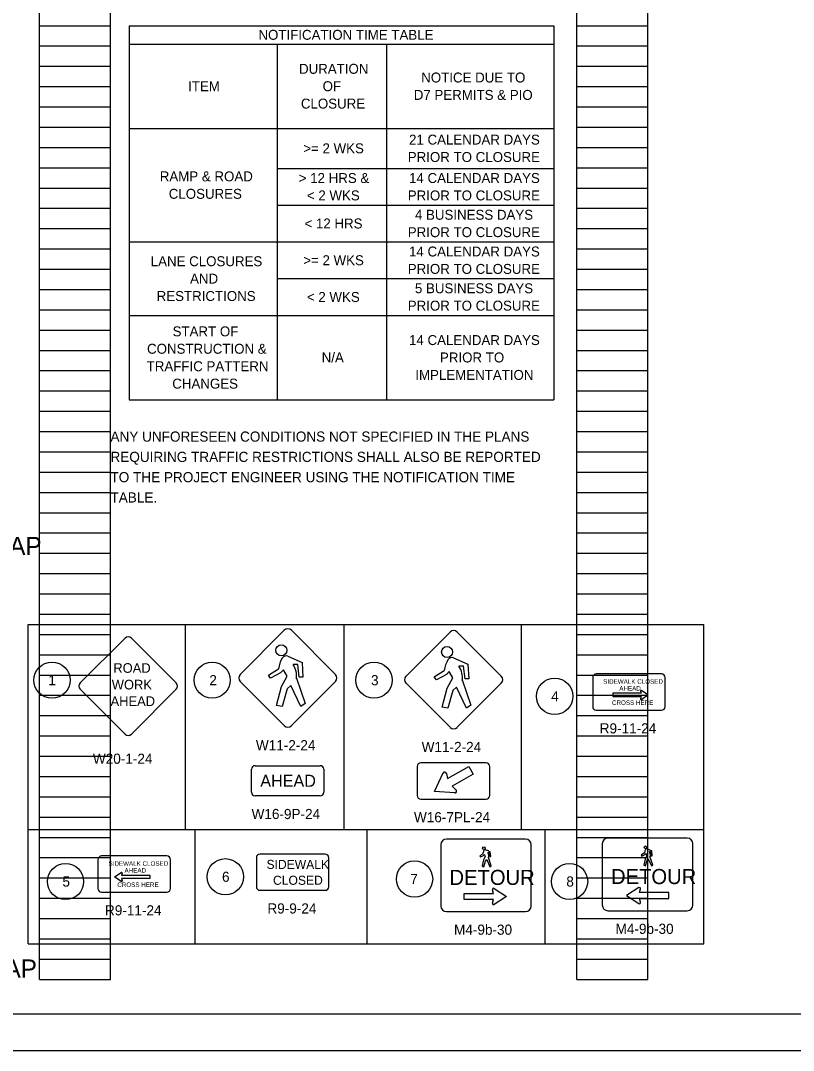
# Model space of a CAD drawing. Extents: x 0 to 34, y 0 to 22.
# Drawn here: x 8.58 to 19.25, y 0 to 14.21 of the extents above; entities that cross this region are included whole.
import ezdxf

# ---------------------------------------------------------------- set-up
doc = ezdxf.new("R2010")
doc.units = 0
for name, color, linetype in [('BR_P_Gen_Text', 7, 'Continuous'), ('Default', 7, 'Continuous'), ('SC_Scratch1', 7, 'Continuous'), ('SH_Border', 7, 'Continuous'), ('SH_Cut_Line', 7, 'Continuous'), ('SH_Text', 7, 'Continuous'), ('SN_P_Signs', 7, 'Continuous'), ('SN_P_Text', 7, 'Continuous')]:
    doc.layers.add(name, color=color, linetype=linetype)

msp = doc.modelspace()

# ---------------------------------------------------------------- linework, layer by layer
at = {"layer": 'SC_Scratch1'}
for p, q in [((8.84, 0.98), (8.84, 21.14)), ((9.82, 0.98), (9.82, 21.14)), ((16.26, 0.98), (16.26, 21.14)), ((17.24, 0.98), (17.24, 21.14)), ((8.84, 14.14), (9.82, 14.14)), ((16.26, 14.14), (17.24, 14.14)), ((8.84, 13.86), (9.82, 13.86)), ((16.26, 13.86), (17.24, 13.86)), ((8.84, 13.58), (9.82, 13.58)), ((16.26, 13.58), (17.24, 13.58)), ((8.84, 13.3), (9.82, 13.3)), ((16.26, 13.3), (17.24, 13.3)), ((8.84, 13.02), (9.82, 13.02)), ((16.26, 13.02), (17.24, 13.02)), ((8.84, 12.74), (9.82, 12.74)), ((16.26, 12.74), (17.24, 12.74)), ((8.84, 12.46), (9.82, 12.46)), ((16.26, 12.46), (17.24, 12.46)), ((8.84, 12.18), (9.82, 12.18)), ((16.26, 12.18), (17.24, 12.18)), ((8.84, 11.9), (9.82, 11.9)), ((16.26, 11.9), (17.24, 11.9)), ((8.84, 11.62), (9.82, 11.62)), ((16.26, 11.62), (17.24, 11.62)), ((8.84, 11.34), (9.82, 11.34)), ((16.26, 11.34), (17.24, 11.34)), ((8.84, 11.06), (9.82, 11.06)), ((16.26, 11.06), (17.24, 11.06)), ((8.84, 10.78), (9.82, 10.78)), ((16.26, 10.78), (17.24, 10.78)), ((8.84, 10.5), (9.82, 10.5)), ((16.26, 10.5), (17.24, 10.5)), ((8.84, 10.22), (9.82, 10.22)), ((16.26, 10.22), (17.24, 10.22)), ((8.84, 9.94), (9.82, 9.94)), ((16.26, 9.94), (17.24, 9.94)), ((8.84, 9.66), (9.82, 9.66)), ((16.26, 9.66), (17.24, 9.66)), ((8.84, 9.38), (9.82, 9.38)), ((16.26, 9.38), (17.24, 9.38)), ((8.84, 9.1), (9.82, 9.1)), ((16.26, 9.1), (17.24, 9.1)), ((8.84, 8.82), (9.82, 8.82)), ((16.26, 8.82), (17.24, 8.82)), ((8.84, 8.54), (9.82, 8.54)), ((16.26, 8.54), (17.24, 8.54)), ((8.84, 8.26), (9.82, 8.26)), ((16.26, 8.26), (17.24, 8.26)), ((8.84, 7.98), (9.82, 7.98)), ((16.26, 7.98), (17.24, 7.98)), ((8.84, 7.7), (9.82, 7.7)), ((16.26, 7.7), (17.24, 7.7)), ((8.84, 7.42), (9.82, 7.42)), ((16.26, 7.42), (17.24, 7.42)), ((8.84, 7.14), (9.82, 7.14)), ((16.26, 7.14), (17.24, 7.14)), ((8.84, 6.86), (9.82, 6.86)), ((16.26, 6.86), (17.24, 6.86)), ((8.84, 6.58), (9.82, 6.58)), ((16.26, 6.58), (17.24, 6.58)), ((8.84, 6.3), (9.82, 6.3)), ((16.26, 6.3), (17.24, 6.3)), ((8.84, 6.02), (9.82, 6.02)), ((16.26, 6.02), (17.24, 6.02)), ((8.84, 5.74), (9.82, 5.74)), ((16.26, 5.74), (17.24, 5.74)), ((8.84, 5.46), (9.82, 5.46)), ((16.26, 5.46), (17.24, 5.46)), ((8.84, 5.18), (9.82, 5.18)), ((16.26, 5.18), (17.24, 5.18)), ((8.84, 4.9), (9.82, 4.9)), ((16.26, 4.9), (17.24, 4.9)), ((8.84, 4.62), (9.82, 4.62)), ((16.26, 4.62), (17.24, 4.62)), ((8.84, 4.34), (9.82, 4.34)), ((16.26, 4.34), (17.24, 4.34)), ((8.84, 4.06), (9.82, 4.06)), ((16.26, 4.06), (17.24, 4.06)), ((8.84, 3.78), (9.82, 3.78)), ((16.26, 3.78), (17.24, 3.78)), ((8.84, 3.5), (9.82, 3.5)), ((16.26, 3.5), (17.24, 3.5)), ((8.84, 3.22), (9.82, 3.22)), ((16.26, 3.22), (17.24, 3.22)), ((8.84, 2.94), (9.82, 2.94)), ((16.26, 2.94), (17.24, 2.94)), ((8.84, 2.66), (9.82, 2.66)), ((16.26, 2.66), (17.24, 2.66)), ((8.84, 2.38), (9.82, 2.38)), ((16.26, 2.38), (17.24, 2.38)), ((8.84, 2.1), (9.82, 2.1)), ((16.26, 2.1), (17.24, 2.1)), ((8.84, 1.82), (9.82, 1.82)), ((16.26, 1.82), (17.24, 1.82)), ((8.84, 1.54), (9.82, 1.54)), ((16.26, 1.54), (17.24, 1.54)), ((8.84, 1.26), (9.82, 1.26)), ((16.26, 1.26), (17.24, 1.26)), ((8.84, 0.98), (9.82, 0.98)), ((16.26, 0.98), (17.24, 0.98))]:
    msp.add_line(p, q, dxfattribs=at)
at = {"layer": 'SH_Border'}
msp.add_lwpolyline([(1.5, 21.5), (33.5, 21.5), (33.5, 0.5), (1.5, 0.5)], close=True, dxfattribs=at)
at = {"layer": 'SH_Cut_Line'}
msp.add_lwpolyline([(0, 0), (34, 0), (34, 22), (0, 22)], close=True, dxfattribs=at)
at = {"layer": 'SH_Text'}
for p, q in [((10.079, 14.14), (15.94, 14.14)), ((10.079, 14.14), (10.079, 8.979)), ((15.94, 14.14), (15.94, 8.979)), ((10.079, 13.886), (15.94, 13.886)), ((12.122, 13.886), (12.122, 8.979)), ((13.629, 13.886), (13.629, 8.979)), ((10.079, 12.723), (15.94, 12.723)), ((12.122, 12.171), (15.94, 12.171)), ((12.122, 11.664), (15.94, 11.664)), ((10.079, 11.157), (15.94, 11.157)), ((12.122, 10.65), (15.94, 10.65)), ((10.079, 10.143), (15.94, 10.143)), ((10.079, 8.979), (15.94, 8.979)), ((8.684, 1.469), (8.684, 5.876)), ((8.684, 5.876), (18.009, 5.876)), ((10.857, 3.047), (10.857, 5.876)), ((13.045, 3.047), (13.045, 5.876)), ((15.496, 3.047), (15.496, 5.876)), ((18.009, 1.469), (18.009, 5.876)), ((8.684, 3.047), (18.009, 3.047)), ((10.991, 1.469), (10.991, 3.047)), ((13.366, 1.469), (13.366, 3.047)), ((15.819, 1.469), (15.819, 3.047)), ((8.684, 1.469), (18.009, 1.469))]:
    msp.add_line(p, q, dxfattribs=at)
for centre in [(9.013, 5.109), (11.224, 5.109), (13.458, 5.109), (15.952, 4.886), (9.2, 2.33), (11.406, 2.396), (14.018, 2.365), (16.158, 2.331)]:
    msp.add_circle(centre, 0.25, dxfattribs=at)
at = {"layer": 'SN_P_Signs'}
for p, q in [((12.268, 5.441), (12.466, 5.354)), ((14.557, 5.418), (14.755, 5.331)), ((12.001, 5.18), (12.14, 5.267)), ((12.407, 5.325), (12.342, 5.325)), ((12.427, 5.151), (12.407, 5.325)), ((12.466, 5.354), (12.476, 5.151)), ((14.695, 5.302), (14.63, 5.302)), ((14.715, 5.127), (14.695, 5.302)), ((14.755, 5.331), (14.765, 5.127)), ((12.031, 5.136), (12.001, 5.18)), ((12.169, 5.209), (12.031, 5.136)), ((12.209, 5.253), (12.169, 5.209)), ((12.179, 5.02), (12.259, 5.165)), ((12.259, 5.165), (12.209, 5.253)), ((12.387, 5.136), (12.506, 4.788)), ((12.476, 5.151), (12.427, 5.151)), ((14.289, 5.156), (14.428, 5.244)), ((14.319, 5.113), (14.289, 5.156)), ((14.458, 5.185), (14.319, 5.113)), ((14.497, 5.229), (14.458, 5.185)), ((14.468, 4.997), (14.547, 5.142)), ((14.547, 5.142), (14.497, 5.229)), ((14.765, 5.127), (14.715, 5.127)), ((12.11, 4.759), (12.179, 5.02)), ((12.259, 4.991), (12.189, 4.745)), ((12.308, 5.035), (12.259, 4.991)), ((12.447, 4.745), (12.308, 5.035)), ((14.398, 4.735), (14.468, 4.997)), ((14.596, 5.011), (14.547, 4.968)), ((14.735, 4.721), (14.596, 5.011)), ((14.676, 5.113), (14.794, 4.764)), ((14.547, 4.968), (14.478, 4.721)), ((17.145, 4.928), (16.755, 4.928)), ((16.755, 4.928), (16.755, 4.882)), ((17.137, 4.957), (17.146, 4.928)), ((17.146, 4.882), (17.137, 4.853)), ((17.146, 4.928), (17.145, 4.928)), ((17.239, 4.905), (17.151, 4.967)), ((17.151, 4.843), (17.239, 4.905)), ((12.189, 4.745), (12.11, 4.759)), ((12.506, 4.788), (12.447, 4.745)), ((14.478, 4.721), (14.398, 4.735)), ((14.794, 4.764), (14.735, 4.721)), ((14.475, 3.75), (14.766, 3.918)), ((14.766, 3.918), (14.827, 3.813)), ((14.459, 3.822), (14.475, 3.75)), ((14.827, 3.813), (14.535, 3.645)), ((14.535, 3.645), (14.59, 3.595)), ((14.572, 3.553), (14.572, 3.553)), ((14.961, 2.716), (14.917, 2.682)), ((14.97, 2.69), (14.98, 2.708)), ((14.98, 2.708), (14.994, 2.678)), ((15.031, 2.732), (15.047, 2.732)), ((15.047, 2.732), (15.055, 2.675)), ((15.069, 2.674), (15.064, 2.74)), ((15.064, 2.74), (15.064, 2.74)), ((17.192, 2.727), (17.147, 2.694)), ((17.156, 2.681), (17.2, 2.701)), ((17.2, 2.701), (17.21, 2.72)), ((17.21, 2.72), (17.225, 2.69)), ((17.261, 2.744), (17.277, 2.743)), ((17.277, 2.743), (17.285, 2.687)), ((17.299, 2.686), (17.294, 2.752)), ((17.294, 2.752), (17.294, 2.752)), ((14.917, 2.682), (14.926, 2.669)), ((14.926, 2.669), (14.97, 2.69)), ((14.97, 2.629), (14.952, 2.546)), ((14.984, 2.658), (14.97, 2.629)), ((14.975, 2.534), (14.998, 2.613)), ((14.994, 2.678), (14.984, 2.658)), ((14.998, 2.613), (15.014, 2.633)), ((15.014, 2.633), (15.057, 2.533)), ((15.038, 2.663), (15.04, 2.665)), ((15.077, 2.547), (15.038, 2.663)), ((15.055, 2.675), (15.069, 2.674)), ((17.147, 2.694), (17.156, 2.681)), ((17.201, 2.641), (17.182, 2.558)), ((17.214, 2.67), (17.201, 2.641)), ((17.205, 2.546), (17.228, 2.624)), ((17.225, 2.69), (17.214, 2.67)), ((17.228, 2.624), (17.244, 2.644)), ((17.244, 2.644), (17.288, 2.545)), ((17.268, 2.675), (17.27, 2.677)), ((17.307, 2.559), (17.268, 2.675)), ((17.285, 2.687), (17.299, 2.686)), ((17.288, 2.545), (17.307, 2.559)), ((9.878, 2.394), (9.966, 2.456)), ((9.98, 2.445), (9.971, 2.417)), ((9.971, 2.417), (9.972, 2.417)), ((9.972, 2.417), (10.362, 2.417)), ((10.362, 2.417), (10.362, 2.37)), ((14.952, 2.546), (14.975, 2.534)), ((15.057, 2.533), (15.077, 2.547)), ((17.182, 2.558), (17.205, 2.546)), ((9.966, 2.331), (9.878, 2.394)), ((9.971, 2.37), (9.98, 2.342)), ((14.705, 2.083), (14.705, 2.166)), ((14.705, 2.166), (15.109, 2.166)), ((15.109, 2.166), (15.093, 2.216)), ((15.117, 2.234), (15.288, 2.124)), ((17.114, 2.246), (16.943, 2.136)), ((16.943, 2.136), (17.114, 2.027)), ((17.122, 2.178), (17.138, 2.228)), ((17.526, 2.178), (17.122, 2.178)), ((17.526, 2.094), (17.526, 2.178)), ((15.109, 2.083), (14.705, 2.083)), ((15.093, 2.032), (15.109, 2.083)), ((15.288, 2.124), (15.117, 2.015)), ((17.138, 2.044), (17.122, 2.094)), ((17.122, 2.094), (17.526, 2.094))]:
    msp.add_line(p, q, dxfattribs=at)
for points in [[(9.403, 5.071), (10.021, 5.69)], [(10.11, 5.69), (10.729, 5.071)], [(11.611, 5.188), (12.219, 5.797)], [(12.318, 5.797), (12.927, 5.188)], [(13.9, 5.165), (14.508, 5.773)], [(14.607, 5.773), (15.215, 5.165)], [(16.477, 5.144), (16.477, 4.744)], [(17.427, 5.194), (16.527, 5.194)], [(17.477, 4.744), (17.477, 5.144)], [(10.021, 4.364), (9.403, 4.983)], [(10.729, 4.983), (10.11, 4.364)], [(12.219, 4.481), (11.611, 5.089)], [(12.927, 5.089), (12.318, 4.481)], [(14.508, 4.458), (13.9, 5.066)], [(15.215, 5.066), (14.607, 4.458)], [(16.755, 4.882), (17.145, 4.882)], [(16.527, 4.694), (17.427, 4.694)], [(11.766, 3.562), (11.766, 3.879)], [(11.816, 3.929), (12.716, 3.929)], [(12.766, 3.879), (12.766, 3.562)], [(14.055, 3.918), (14.055, 3.518)], [(15.005, 3.968), (14.105, 3.968)], [(15.055, 3.518), (15.055, 3.918)], [(14.572, 3.553), (14.291, 3.574), (14.413, 3.828)], [(12.716, 3.512), (11.816, 3.512)], [(14.105, 3.468), (15.005, 3.468)], [(15.551, 2.916), (14.457, 2.916)], [(16.61, 2.85), (16.61, 2.006)], [(17.782, 2.928), (16.688, 2.928)], [(17.86, 2.006), (17.86, 2.85)], [(12.784, 2.709), (11.884, 2.709)], [(14.379, 2.838), (14.379, 1.994)], [(15.629, 1.994), (15.629, 2.838)], [(9.648, 2.633), (9.648, 2.233)], [(10.598, 2.683), (9.698, 2.683)], [(10.648, 2.233), (10.648, 2.633)], [(11.834, 2.659), (11.834, 2.259)], [(12.834, 2.259), (12.834, 2.659)], [(10.362, 2.37), (9.972, 2.37)], [(9.698, 2.183), (10.598, 2.183)], [(11.884, 2.209), (12.784, 2.209)], [(14.457, 1.916), (15.551, 1.916)], [(16.688, 1.928), (17.782, 1.928)]]:
    msp.add_lwpolyline(points, dxfattribs=at)
for centre, radius in [((12.179, 5.521), 0.0758), ((14.467, 5.497), 0.0758), ((14.974, 2.79), 0.0191), ((17.205, 2.802), 0.0191)]:
    msp.add_circle(centre, radius, dxfattribs=at)
for centre, radius, start, end in [((10.066, 5.645), 0.0625, 45, 135), ((12.269, 5.747), 0.07, 45, 135), ((14.557, 5.723), 0.07, 45, 135), ((12.617, 5.183), 0.485, 151.5411, 170.0317), ((12.251, 5.368), 0.0751, 76.2441, 142.495), ((14.539, 5.345), 0.0751, 76.2441, 142.495), ((12.108, 5.167), 0.282, 351.8502, 34.0609), ((14.905, 5.16), 0.485, 151.5411, 170.0317), ((14.396, 5.143), 0.282, 351.8502, 34.0609), ((11.661, 5.139), 0.07, 135, 225), ((12.877, 5.139), 0.07, 315, 45), ((13.949, 5.115), 0.07, 135, 225), ((15.165, 5.115), 0.07, 315, 45), ((16.527, 5.144), 0.05, 90, 180), ((17.427, 5.144), 0.05, 0, 90), ((9.447, 5.027), 0.0625, 135, 225), ((10.684, 5.027), 0.0625, 315, 45), ((17.145, 4.96), 0.00912, 54.9207, 197.6378), ((17.145, 4.85), 0.00912, 162.3622, 305.0792), ((16.527, 4.744), 0.05, 180, 270), ((17.427, 4.744), 0.05, 270, 0), ((12.269, 4.531), 0.07, 225, 315), ((14.557, 4.507), 0.07, 225, 315), ((10.066, 4.408), 0.0625, 225, 315), ((11.816, 3.879), 0.05, 90, 180), ((12.716, 3.879), 0.05, 0, 90), ((14.105, 3.918), 0.05, 90, 180), ((14.435, 3.817), 0.0243, 12.1872, 154.3237), ((15.005, 3.918), 0.05, 0, 90), ((11.816, 3.562), 0.05, 180, 270), ((12.716, 3.562), 0.05, 270, 360), ((14.574, 3.577), 0.0243, 265.6763, 47.8128), ((14.105, 3.518), 0.05, 180, 270), ((15.005, 3.518), 0.05, 270, 360), ((14.457, 2.838), 0.0781, 90, 180), ((15.551, 2.838), 0.0781, 0, 90), ((16.688, 2.85), 0.0781, 90, 180), ((17.782, 2.85), 0.0781, 0, 90), ((11.884, 2.659), 0.05, 90, 180), ((12.784, 2.659), 0.05, 0, 90), ((9.698, 2.633), 0.05, 90, 180), ((10.598, 2.633), 0.05, 0, 90), ((9.972, 2.448), 0.00912, 342.3622, 125.0793), ((9.972, 2.339), 0.00912, 234.9208, 17.6378), ((9.698, 2.233), 0.05, 180, 270), ((10.598, 2.233), 0.05, 270, 0), ((11.884, 2.259), 0.05, 180, 270), ((12.784, 2.259), 0.05, 270, 0), ((15.108, 2.221), 0.0156, 57.4015, 196.9519), ((17.123, 2.232), 0.0156, 343.0481, 122.5985), ((14.457, 1.994), 0.0781, 180, 270), ((15.108, 2.028), 0.0156, 163.0481, 302.5985), ((15.551, 1.994), 0.0781, 270, 0), ((16.688, 2.006), 0.0781, 180, 270), ((17.123, 2.04), 0.0156, 237.4015, 16.9519), ((17.782, 2.006), 0.0781, 270, 0)]:
    msp.add_arc(centre, radius, start, end, dxfattribs=at)
for points in [[(15.064, 2.74), (15.044, 2.749), (15.013, 2.763), (15.002, 2.768), (14.998, 2.769), (14.995, 2.769), (14.986, 2.769), (14.974, 2.758), (14.968, 2.742), (14.963, 2.73), (14.961, 2.716)], [(15.04, 2.665), (15.042, 2.669), (15.044, 2.674), (15.044, 2.685), (15.042, 2.695), (15.037, 2.711), (15.034, 2.722), (15.031, 2.732)], [(17.294, 2.752), (17.274, 2.761), (17.244, 2.775), (17.232, 2.78), (17.229, 2.781), (17.225, 2.781), (17.216, 2.781), (17.205, 2.77), (17.199, 2.754), (17.193, 2.741), (17.192, 2.727)], [(17.27, 2.677), (17.273, 2.681), (17.275, 2.686), (17.274, 2.697), (17.272, 2.707), (17.268, 2.723), (17.264, 2.734), (17.261, 2.744)]]:
    msp.add_open_spline(points, degree=3, dxfattribs=at)

# ---------------------------------------------------------------- texts
at = {"layer": 'BR_P_Gen_Text'}
for p in [(2.07, 6.836), (2.005, 1.005)]:
    msp.add_text('AUG-274-0431 PEDESTRIAN DETOUR MAP', height=0.25, dxfattribs=at).set_placement(p)
at = {"layer": 'Default'}
for s, p in [('1', (8.963, 5.039)), ('2', (11.185, 5.039)), ('3', (13.417, 5.039)), ('4', (15.904, 4.816)), ('6', (11.36, 2.326)), ('7', (13.959, 2.295)), ('5', (9.157, 2.26)), ('8', (16.113, 2.261))]:
    msp.add_text(s, height=0.14, dxfattribs=at).set_placement(p)
at = {"layer": 'SH_Text'}
for s, height, p in [('NOTIFICATION TIME TABLE', 0.13722, (11.863, 13.945)), ('DURATION ', 0.1372, (12.423, 13.476)), ('ITEM', 0.1372, (10.892, 13.236)), ('OF ', 0.1372, (12.749, 13.236)), ('NOTICE DUE TO ', 0.13722, (14.11, 13.356)), ('D7 PERMITS & PIO', 0.13722, (14.007, 13.116)), ('CLOSURE', 0.1372, (12.449, 12.996)), ('>= 2 WKS', 0.1372, (12.482, 12.379)), ('21 CALENDAR DAYS ', 0.13722, (13.942, 12.499)), ('PRIOR TO CLOSURE', 0.13722, (13.924, 12.259)), ('RAMP & ROAD ', 0.13722, (10.501, 11.992)), ('> 12 HRS & ', 0.13722, (12.419, 11.969)), ('14 CALENDAR DAYS ', 0.13722, (13.942, 11.969)), ('CLOSURES', 0.1372, (10.625, 11.751)), ('< 2 WKS', 0.1372, (12.532, 11.729)), ('PRIOR TO CLOSURE', 0.13722, (13.924, 11.729)), ('4 BUSINESS DAYS ', 0.13722, (14.023, 11.462)), ('< 12 HRS', 0.1372, (12.499, 11.342)), ('PRIOR TO CLOSURE', 0.13722, (13.924, 11.222)), ('14 CALENDAR DAYS ', 0.13722, (13.942, 10.955)), ('LANE CLOSURES ', 0.13722, (10.376, 10.821)), ('>= 2 WKS', 0.1372, (12.482, 10.835)), ('PRIOR TO CLOSURE', 0.13722, (13.924, 10.715)), ('AND ', 0.1372, (10.919, 10.581)), ('5 BUSINESS DAYS ', 0.13722, (14.023, 10.448)), ('RESTRICTIONS', 0.13722, (10.458, 10.341)), ('< 2 WKS', 0.1372, (12.532, 10.328)), ('PRIOR TO CLOSURE', 0.13722, (13.924, 10.208)), ('START OF ', 0.1372, (10.678, 9.853)), ('14 CALENDAR DAYS ', 0.13722, (13.942, 9.733)), ('CONSTRUCTION & ', 0.13722, (10.325, 9.613)), ('N/A', 0.1372, (12.736, 9.493)), ('PRIOR TO ', 0.1372, (14.369, 9.493)), ('TRAFFIC PATTERN', 0.13722, (10.32, 9.372)), ('IMPLEMENTATION', 0.13722, (14.028, 9.252)), ('CHANGES', 0.1372, (10.673, 9.132)), ('ANY UNFORESEEN CONDITIONS NOT SPECIFIED IN THE PLANS', 0.14, (9.82, 8.4)), ('REQUIRING TRAFFIC RESTRICTIONS SHALL ALSO BE REPORTED', 0.14, (9.82, 8.12)), ('TO THE PROJECT ENGINEER USING THE NOTIFICATION TIME', 0.14, (9.82, 7.84)), ('TABLE.', 0.14, (9.82, 7.56))]:
    msp.add_text(s, height=height, dxfattribs=at).set_placement(p)
at = {"layer": 'SN_P_Signs'}
for s, height, p in [('ROAD', 0.1333, (9.86, 5.21)), ('WORK', 0.1333, (9.838, 4.981)), ('SIDEWALK CLOSED', 0.0625, (16.622, 5.059)), ('AHEAD', 0.0625, (16.844, 4.965)), (' AHEAD ', 0.1333, (9.772, 4.752)), ('CROSS HERE', 0.0625, (16.743, 4.767)), ('AHEAD', 0.1667, (11.888, 3.637)), ('SIDEWALK CLOSED', 0.0625, (9.793, 2.547)), ('SIDEWALK', 0.125, (11.974, 2.504)), ('AHEAD', 0.0625, (10.014, 2.453)), ('DETOUR', 0.2084, (14.5, 2.283)), ('DETOUR', 0.2084, (16.73, 2.295)), ('CROSS HERE', 0.0625, (9.914, 2.255)), ('CLOSED', 0.125, (12.064, 2.285))]:
    msp.add_text(s, height=height, dxfattribs=at).set_placement(p)
at = {"layer": 'SN_P_Text'}
for s, p in [('R9-11-24', (16.574, 4.374)), ('W11-2-24', (11.828, 4.141)), ('W11-2-24', (14.116, 4.117)), ('W20-1-24', (9.578, 3.955)), ('W16-9P-24', (11.768, 3.192)), ('W16-7PL-24', (14.01, 3.148)), ('R9-11-24', (9.745, 1.863)), ('R9-9-24', (11.987, 1.889)), ('M4-9b-30', (14.563, 1.596)), ('M4-9b-30', (16.793, 1.608))]:
    msp.add_text(s, height=0.14, dxfattribs=at).set_placement(p)

doc.saveas('drawing.dxf')
